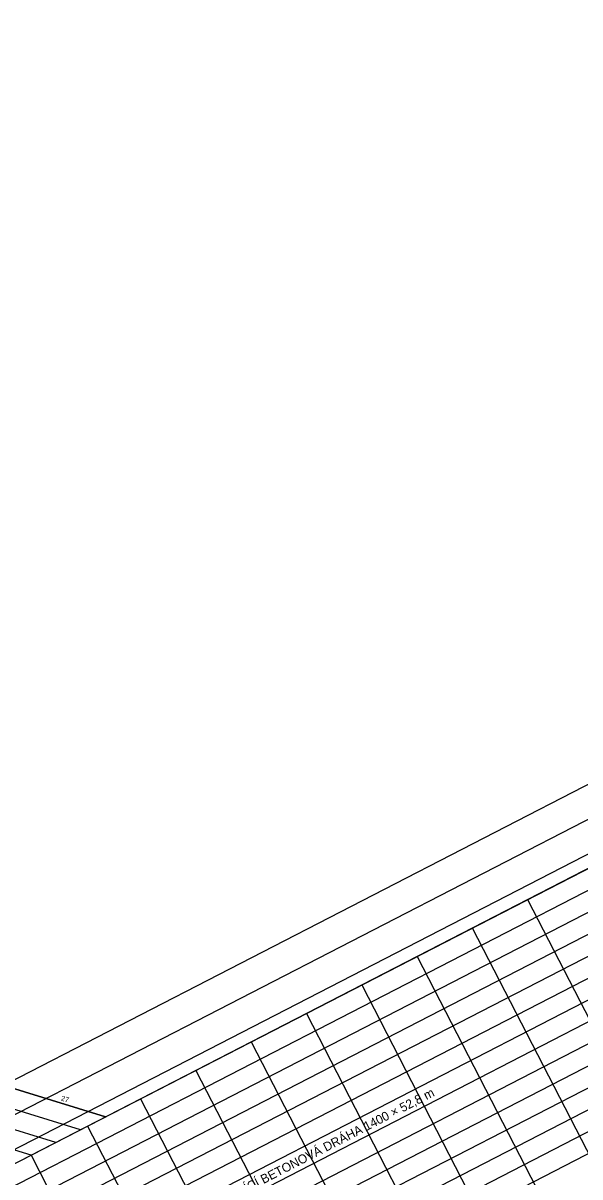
# Model space of a CAD drawing. Extents: x -886320 to -884760, y -1024172 to -1023483.
# Drawn here: x -885881.5 to -885773.4, y -1024051.4 to -1023827.5 of the extents above; entities that cross this region are included whole.
import ezdxf

# ---------------------------------------------------------------- set-up
doc = ezdxf.new("R2010")
doc.units = 0
for name, color, linetype in [('AGA__Netisknout', 7, 'Continuous'), ('Stavajici_betonova_draha', 7, 'Continuous'), ('Stavajici_betonova_draha_osa', 7, 'Continuous'), ('Stavajici_betonova_draha_popis', 7, 'Continuous'), ('Stavajici_betonova_draha_Popis desky', 7, 'Continuous'), ('Stavajici_betonova_draha_Spára', 7, 'Continuous'), ('Stavajici_drahovy_system_TWY', 7, 'Continuous'), ('Stavajici_drahovy_system_TWY_osy', 7, 'Continuous')]:
    doc.layers.add(name, color=color, linetype=linetype)

msp = doc.modelspace()

# ---------------------------------------------------------------- linework, layer by layer
at = {"layer": 'AGA__Netisknout'}
msp.add_line((-886017.78, -1024147.99), (-884773.13, -1023507.02), dxfattribs=at)
at = {"layer": 'Stavajici_betonova_draha'}
for p, q in [((-886029.69, -1024124.32), (-884785.04, -1023483.35)), ((-886029.69, -1024124.32), (-884785.04, -1023483.35)), ((-886315.74, -1023900.86), (-885865.51, -1024039.77))]:
    msp.add_line(p, q, dxfattribs=at)
at = {"layer": 'Stavajici_betonova_draha_osa'}
msp.add_line((-886017.55, -1024147.88), (-884772.9, -1023506.91), dxfattribs=at)
at = {"layer": 'Stavajici_betonova_draha_Spára'}
for p, q in [((-886029.91, -1024124.43), (-884785.26, -1023483.46)), ((-886028.18, -1024127.8), (-884783.53, -1023486.82)), ((-886026.44, -1024131.16), (-884781.79, -1023490.19)), ((-886024.71, -1024134.53), (-884780.06, -1023493.56)), ((-886022.98, -1024137.89), (-884778.33, -1023496.92)), ((-886021.24, -1024141.26), (-884776.59, -1023500.29)), ((-886019.51, -1024144.63), (-884774.86, -1023503.65)), ((-886016.04, -1024151.36), (-884771.39, -1023510.39)), ((-886014.31, -1024154.72), (-884769.66, -1023513.75)), ((-886012.58, -1024158.09), (-884767.93, -1023517.12)), ((-886010.84, -1024161.46), (-884766.19, -1023520.48)), ((-886009.11, -1024164.82), (-884764.46, -1023523.85)), ((-886007.38, -1024168.19), (-884762.73, -1023527.21)), ((-885865.51, -1024039.77), (-886315.74, -1023900.86)), ((-885870.32, -1024042.24), (-886316.86, -1023904.48)), ((-885875.13, -1024044.72), (-886317.98, -1023908.1)), ((-885879.94, -1024047.2), (-886319.09, -1023911.72)), ((-885783.56, -1023997.57), (-885759.29, -1024044.69)), ((-885794.29, -1024003.09), (-885770.02, -1024050.21)), ((-885805.02, -1024008.62), (-885780.75, -1024055.74)), ((-885815.75, -1024014.14), (-885791.48, -1024061.27)), ((-885826.48, -1024019.67), (-885802.21, -1024066.79)), ((-885837.21, -1024025.19), (-885812.94, -1024072.32)), ((-885847.94, -1024030.72), (-885823.67, -1024077.84)), ((-885858.67, -1024036.25), (-885834.4, -1024083.37)), ((-885868.96, -1024041.55), (-885844.7, -1024088.67)), ((-885879.94, -1024047.2), (-885855.67, -1024094.32))]:
    msp.add_line(p, q, dxfattribs=at)
at = {"layer": 'Stavajici_drahovy_system_TWY'}
for p, q in [((-885887.27, -1024034.67), (-884885.91, -1023518.99)), ((-885886.13, -1024047.58), (-885758.79, -1023982))]:
    msp.add_line(p, q, dxfattribs=at)
at = {"layer": 'Stavajici_drahovy_system_TWY_osy'}
msp.add_line((-885886.7, -1024041.13), (-884883.17, -1023524.32), dxfattribs=at)

# ---------------------------------------------------------------- texts
at = {"layer": 'Stavajici_betonova_draha_popis'}
msp.add_text('STÁVAJÍCÍ BETONOVÁ DRÁHA 1400 × 52,8 m', height=1.75, rotation=27.2477, dxfattribs=at).set_placement((-885845.92, -1024058.51))
at = {"layer": 'Stavajici_betonova_draha_Popis desky'}
msp.add_text('27', height=1, rotation=342.8547, dxfattribs=at).set_placement((-885874.22, -1024036.55))

doc.saveas('drawing.dxf')
